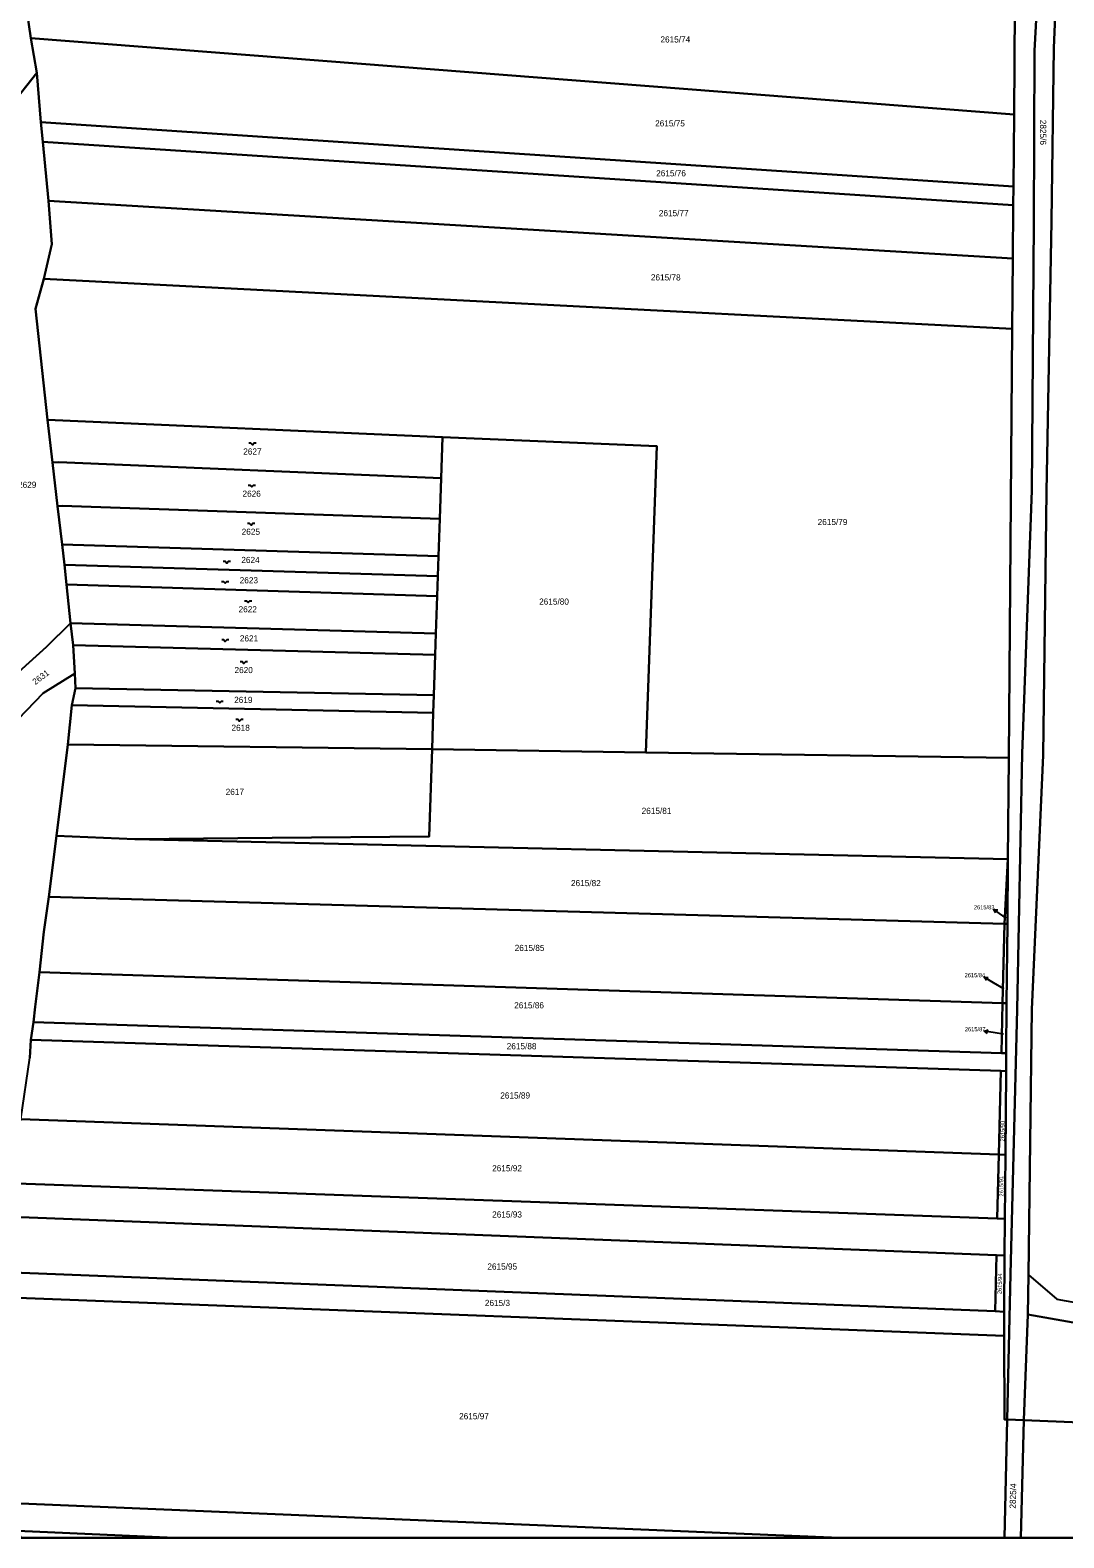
# Model space of a CAD drawing. Extents: x -596024 to -594475, y -1163820 to -1161957.
# Drawn here: x -595164.4 to -594879.1, y -1163820.2 to -1163404 of the extents above; entities that cross this region are included whole.
import ezdxf

# ---------------------------------------------------------------- set-up
doc = ezdxf.new("R2010")
doc.units = 0
for name, color, linetype in [('Level 1', 7, 'Continuous'), ('Level 4', 7, 'Continuous'), ('Level 5', 7, 'Continuous'), ('Level 57', 7, 'Continuous'), ('Level 60', 7, 'Continuous'), ('Vrstva 60', 7, 'Continuous'), ('Vrstva 63', 7, 'Continuous')]:
    doc.layers.add(name, color=color, linetype=linetype)

msp = doc.modelspace()

# ---------------------------------------------------------------- linework, layer by layer
at = {"layer": 'Level 1'}
for p, q in [((-594895.48, -1163820.23), (-594894.71, -1163787.59)), ((-594890.11, -1163787.78), (-594890.98, -1163820.23)), ((-595171.38, -1163810.61), (-594941.03, -1163820.23)), ((-595167.87, -1163818.34), (-595124.58, -1163820.23))]:
    msp.add_line(p, q, dxfattribs=at)
for points in [[(-594894.71, -1163787.59), (-594893.79, -1163747.41), (-594892.03, -1163674.4), (-594890.62, -1163603.73), (-594887.9, -1163531.14), (-594887.39, -1163457.21), (-594887.16, -1163409.69), (-594885.8, -1163384.09), (-594882.1, -1163335.97), (-594881.32, -1163308.47), (-594889.29, -1163183.24), (-594889.61, -1163167.04), (-594890.11, -1163145.09)], [(-594888.88, -1163747.67), (-594887.95, -1163674.37), (-594884.78, -1163604.15), (-594883.87, -1163531.43), (-594882.54, -1163456.78), (-594881.9, -1163408.92), (-594880.83, -1163384.76), (-594876.89, -1163338.79)], [(-595164.21, -1163406.27), (-595168.62, -1163375.94)], [(-594892.61, -1163398), (-594892.85, -1163427.31)], [(-594892.85, -1163427.31), (-595164.21, -1163406.27)], [(-595164.21, -1163406.27), (-595162.62, -1163415.85)], [(-595169.81, -1163424.99), (-595162.62, -1163415.85)], [(-595162.62, -1163415.85), (-595161.46, -1163429.42)], [(-594893.01, -1163447.21), (-594892.85, -1163427.31)], [(-595161.46, -1163429.42), (-595160.94, -1163434.83)], [(-595161.46, -1163429.42), (-594893.01, -1163447.21)], [(-595160.94, -1163434.83), (-595159.39, -1163451.17)], [(-594893.06, -1163452.31), (-595160.94, -1163434.83)], [(-594893.01, -1163447.21), (-594893.06, -1163452.31)], [(-595160.65, -1163472.63), (-595158.4, -1163463.07), (-595159.39, -1163451.17)], [(-595159.39, -1163451.17), (-594893.18, -1163467.09)], [(-594893.06, -1163452.31), (-594893.18, -1163467.09)], [(-594893.18, -1163467.09), (-594893.34, -1163486.47)], [(-595159.6, -1163511.56), (-595162.92, -1163480.95), (-595160.65, -1163472.63)], [(-594893.34, -1163486.47), (-595160.65, -1163472.63)], [(-594893.34, -1163486.47), (-594894.33, -1163604.93)], [(-595159.6, -1163511.56), (-595050.61, -1163516.35)], [(-595158.22, -1163523.39), (-595159.6, -1163511.56)], [(-595050.99, -1163527.66), (-595050.61, -1163516.35)], [(-594994.44, -1163603.44), (-594991.44, -1163518.91), (-595050.61, -1163516.35)], [(-595158.22, -1163523.39), (-595156.51, -1163523.29), (-595050.99, -1163527.66)], [(-595156.83, -1163535.39), (-595158.22, -1163523.39)], [(-595051.37, -1163538.89), (-595050.99, -1163527.66)], [(-595156.83, -1163535.39), (-595155.55, -1163535.32), (-595051.37, -1163538.89)], [(-595155.59, -1163546.03), (-595156.83, -1163535.39)], [(-595051.71, -1163549.26), (-595051.37, -1163538.89)], [(-595051.71, -1163549.26), (-595155.59, -1163546.03)], [(-595154.91, -1163551.65), (-595155.59, -1163546.03)], [(-595154.91, -1163551.65), (-595051.9, -1163554.78)], [(-595154.39, -1163557.04), (-595154.91, -1163551.65)], [(-595051.9, -1163554.78), (-595051.71, -1163549.26)], [(-595052.08, -1163560.23), (-595051.9, -1163554.78)], [(-595052.08, -1163560.23), (-595154.39, -1163557.04)], [(-595153.32, -1163567.77), (-595154.39, -1163557.04)], [(-595052.43, -1163570.6), (-595052.08, -1163560.23)], [(-595173.55, -1163598.4), (-595171.45, -1163584.7), (-595159.88, -1163574.29), (-595153.32, -1163567.77)], [(-595153.32, -1163567.77), (-595052.43, -1163570.6)], [(-595152.55, -1163573.8), (-595153.32, -1163567.77)], [(-595052.62, -1163576.43), (-595052.43, -1163570.6)], [(-595152.12, -1163581.59), (-595152.55, -1163573.8)], [(-595052.62, -1163576.43), (-595152.55, -1163573.8)], [(-595052.99, -1163587.58), (-595052.62, -1163576.43)], [(-595152.12, -1163581.59), (-595160.81, -1163587.04), (-595167.71, -1163594.27), (-595170.35, -1163599.68), (-595174.49, -1163637.45), (-595176.11, -1163658.53), (-595174.49, -1163676.29), (-595174.69, -1163688.93), (-595176.27, -1163699.8), (-595179.65, -1163708.43), (-595181.95, -1163711.02), (-595190.69, -1163714.93), (-595195.82, -1163716.42)], [(-595151.89, -1163585.68), (-595152.12, -1163581.59)], [(-595152.94, -1163590.36), (-595151.89, -1163585.68)], [(-595151.89, -1163585.68), (-595052.99, -1163587.58)], [(-595053.16, -1163592.45), (-595052.99, -1163587.58)], [(-595154.03, -1163601.25), (-595152.94, -1163590.36)], [(-595152.94, -1163590.36), (-595053.16, -1163592.45)], [(-595053.49, -1163602.5), (-595053.16, -1163592.45)], [(-595157.12, -1163626.46), (-595154.03, -1163601.25)], [(-595154.03, -1163601.25), (-595053.49, -1163602.5)], [(-595135.55, -1163627.33), (-595097.61, -1163626.99), (-595054.3, -1163626.6), (-595053.49, -1163602.5)], [(-595053.49, -1163602.5), (-594994.44, -1163603.44)], [(-594894.33, -1163604.93), (-594994.44, -1163603.44)], [(-594894.33, -1163604.93), (-594894.56, -1163632.87)], [(-595157.12, -1163626.46), (-595159.23, -1163643.27)], [(-595157.12, -1163626.46), (-595135.55, -1163627.33)], [(-594894.56, -1163632.87), (-595135.55, -1163627.33)], [(-594895.48, -1163650.69), (-594894.56, -1163632.87)], [(-594894.56, -1163632.87), (-594894.7, -1163650.71)], [(-595161.84, -1163664.1), (-595160.69, -1163652.94), (-595159.23, -1163643.27)], [(-595159.23, -1163643.27), (-594895.48, -1163650.69)], [(-594895.48, -1163650.69), (-594896.02, -1163672.62)], [(-594894.7, -1163650.71), (-594895.48, -1163650.69)], [(-594894.89, -1163672.67), (-594894.7, -1163650.71)], [(-595163.49, -1163677.92), (-595163, -1163673.62), (-595161.84, -1163664.1)], [(-594896.02, -1163672.62), (-595161.84, -1163664.1)], [(-594896.35, -1163686.42), (-594896.02, -1163672.62)], [(-594896.02, -1163672.62), (-594894.89, -1163672.67)], [(-594894.89, -1163672.67), (-594895, -1163686.46)], [(-595164.26, -1163682.78), (-595163.49, -1163677.92)], [(-595163.49, -1163677.92), (-594896.35, -1163686.42)], [(-595166.98, -1163704.63), (-595164.54, -1163687.76), (-595164.26, -1163682.78)], [(-594896.47, -1163691.35), (-595164.26, -1163682.78)], [(-594895, -1163686.46), (-594896.35, -1163686.42)], [(-594895.04, -1163691.39), (-594895, -1163686.46)], [(-594897.04, -1163714.39), (-594896.47, -1163691.35)], [(-594896.47, -1163691.35), (-594895.04, -1163691.39)], [(-594895.04, -1163691.39), (-594895.23, -1163714.46)], [(-595166.98, -1163704.63), (-594897.04, -1163714.39)], [(-594897.48, -1163732.08), (-594897.04, -1163714.39)], [(-594895.23, -1163714.46), (-594897.04, -1163714.39)], [(-594895.37, -1163732.16), (-594895.23, -1163714.46)], [(-595173.34, -1163722.2), (-594897.48, -1163732.08)], [(-595176.58, -1163731.36), (-594897.72, -1163742.15)], [(-594897.48, -1163732.08), (-594895.37, -1163732.16)], [(-594895.37, -1163732.16), (-594895.46, -1163742.25)], [(-594897.72, -1163742.15), (-594898.1, -1163757.7)], [(-594895.46, -1163742.25), (-594897.72, -1163742.15)], [(-594895.59, -1163757.8), (-594895.46, -1163742.25)], [(-594898.1, -1163757.7), (-595178.58, -1163746.62)], [(-594888.88, -1163747.67), (-594889.06, -1163758.56)], [(-594888.88, -1163747.67), (-594881.07, -1163754.37), (-594853.71, -1163759.18), (-594809.52, -1163766.35), (-594779.42, -1163772.07), (-594705.71, -1163784.41), (-594630.48, -1163797), (-594524.52, -1163814.91)], [(-595177.46, -1163753.59), (-594895.57, -1163764.46)], [(-594895.59, -1163757.8), (-594898.1, -1163757.7)], [(-594895.59, -1163757.8), (-594895.57, -1163764.46)], [(-594889.06, -1163758.56), (-594890.11, -1163787.78)], [(-594661.02, -1163797.43), (-594706.83, -1163789.82), (-594781.05, -1163777.75), (-594810.04, -1163772.05), (-594854.05, -1163764.77), (-594889.06, -1163758.56)], [(-594895.57, -1163764.46), (-594895.52, -1163787.56), (-594894.71, -1163787.59)], [(-594894.71, -1163787.59), (-594890.11, -1163787.78)], [(-594890.11, -1163787.78), (-594739.19, -1163793.96)]]:
    msp.add_lwpolyline(points, dxfattribs=at)
at = {"layer": 'Level 5'}
for points in [[(-595104.07, -1163517.99), (-595103.57, -1163517.99), (-595103.07, -1163518.49), (-595102.57, -1163517.99), (-595102.07, -1163517.99)], [(-595104.25, -1163529.63), (-595103.75, -1163529.63), (-595103.25, -1163530.13), (-595102.75, -1163529.63), (-595102.25, -1163529.63)], [(-595104.44, -1163540.14), (-595103.94, -1163540.14), (-595103.44, -1163540.64), (-595102.94, -1163540.14), (-595102.44, -1163540.14)], [(-595111.13, -1163550.63), (-595110.63, -1163550.63), (-595110.13, -1163551.13), (-595109.63, -1163550.63), (-595109.13, -1163550.63)], [(-595111.59, -1163556.23), (-595111.09, -1163556.23), (-595110.59, -1163556.73), (-595110.09, -1163556.23), (-595109.59, -1163556.23)], [(-595105.26, -1163561.54), (-595104.76, -1163561.54), (-595104.26, -1163562.04), (-595103.76, -1163561.54), (-595103.26, -1163561.54)], [(-595111.55, -1163572.27), (-595111.05, -1163572.27), (-595110.55, -1163572.77), (-595110.05, -1163572.27), (-595109.55, -1163572.27)], [(-595106.43, -1163578.32), (-595105.93, -1163578.32), (-595105.43, -1163578.82), (-595104.93, -1163578.32), (-595104.43, -1163578.32)], [(-595113.11, -1163589.26), (-595112.61, -1163589.26), (-595112.11, -1163589.76), (-595111.61, -1163589.26), (-595111.11, -1163589.26)], [(-595107.63, -1163594.25), (-595107.13, -1163594.25), (-595106.63, -1163594.75), (-595106.13, -1163594.25), (-595105.63, -1163594.25)]]:
    msp.add_lwpolyline(points, dxfattribs=at)
at = {"layer": 'Level 57'}
for p, q in [((-594895.98, -1163648.49), (-594898.41, -1163646.73)), ((-594895.04, -1163649.16), (-594895.98, -1163648.49)), ((-594898.49, -1163666.99), (-594901.08, -1163665.47)), ((-594895.64, -1163668.66), (-594898.49, -1163666.99)), ((-594898.08, -1163680.82), (-594901.05, -1163680.38)), ((-594895.72, -1163681.18), (-594898.08, -1163680.82))]:
    msp.add_line(p, q, dxfattribs=at)
for points in [[(-594897.89, -1163647.72), (-594898.41, -1163646.73), (-594897.31, -1163646.91)], [(-594900.47, -1163666.41), (-594901.08, -1163665.47), (-594899.96, -1163665.54)], [(-594900.14, -1163681.02), (-594901.05, -1163680.38), (-594899.99, -1163680.03)]]:
    msp.add_lwpolyline(points, dxfattribs=at)
at = {"layer": 'Level 60'}
for points in [[(-594876.89, -1163338.79), (-594880.83, -1163384.76), (-594881.9, -1163408.92), (-594882.54, -1163456.78), (-594883.87, -1163531.43), (-594884.78, -1163604.15), (-594887.95, -1163674.37), (-594888.88, -1163747.67), (-594889.06, -1163758.56), (-594890.11, -1163787.78), (-594894.71, -1163787.59), (-594893.79, -1163747.41), (-594892.03, -1163674.4), (-594890.62, -1163603.73), (-594887.9, -1163531.14), (-594887.39, -1163457.21), (-594887.16, -1163409.69), (-594885.8, -1163384.09), (-594882.1, -1163335.97), (-594881.32, -1163308.47), (-594889.29, -1163183.24), (-594889.61, -1163167.04), (-594890.11, -1163145.09)], [(-594885.8, -1163384.09), (-594887.16, -1163409.69), (-594887.39, -1163457.21), (-594887.9, -1163531.14), (-594890.62, -1163603.73), (-594892.03, -1163674.4), (-594893.79, -1163747.41), (-594894.71, -1163787.59), (-594895.52, -1163787.56), (-594895.57, -1163764.46), (-594895.59, -1163757.8), (-594895.46, -1163742.25), (-594895.37, -1163732.16), (-594895.23, -1163714.46), (-594895.04, -1163691.39), (-594895, -1163686.46), (-594894.89, -1163672.67), (-594894.7, -1163650.71), (-594894.56, -1163632.87), (-594894.33, -1163604.93), (-594893.34, -1163486.47), (-594893.18, -1163467.09), (-594893.06, -1163452.31), (-594893.01, -1163447.21), (-594892.85, -1163427.31), (-594892.61, -1163398)], [(-595169.81, -1163424.99), (-595162.62, -1163415.85), (-595161.46, -1163429.42), (-595160.94, -1163434.83), (-595159.39, -1163451.17), (-595158.4, -1163463.07), (-595160.65, -1163472.63), (-595162.92, -1163480.95), (-595159.6, -1163511.56), (-595158.22, -1163523.39), (-595156.83, -1163535.39), (-595155.59, -1163546.03), (-595154.91, -1163551.65), (-595154.39, -1163557.04), (-595153.32, -1163567.77), (-595159.88, -1163574.29), (-595171.45, -1163584.7)], [(-595171.45, -1163584.7), (-595159.88, -1163574.29), (-595153.32, -1163567.77), (-595152.55, -1163573.8), (-595152.12, -1163581.59), (-595160.81, -1163587.04), (-595167.71, -1163594.27)], [(-595167.71, -1163594.27), (-595160.81, -1163587.04), (-595152.12, -1163581.59), (-595151.89, -1163585.68), (-595152.94, -1163590.36), (-595154.03, -1163601.25), (-595157.12, -1163626.46), (-595159.23, -1163643.27), (-595160.69, -1163652.94), (-595161.84, -1163664.1), (-595163, -1163673.62), (-595163.49, -1163677.92), (-595164.26, -1163682.78), (-595164.54, -1163687.76)]]:
    msp.add_lwpolyline(points, dxfattribs=at)
for points in [[(-595169.37, -1163381.98), (-595168.62, -1163375.94), (-595164.21, -1163406.27), (-595162.62, -1163415.85), (-595169.81, -1163424.99), (-595173.36, -1163424.93), (-595171.94, -1163414.75), (-595170.3, -1163393.85)], [(-595168.62, -1163375.94), (-594892.61, -1163398), (-594892.85, -1163427.31), (-595164.21, -1163406.27)], [(-595164.21, -1163406.27), (-594892.85, -1163427.31), (-594893.01, -1163447.21), (-595161.46, -1163429.42), (-595162.62, -1163415.85)], [(-595160.94, -1163434.83), (-595161.46, -1163429.42), (-594893.01, -1163447.21), (-594893.06, -1163452.31)], [(-595159.39, -1163451.17), (-595160.94, -1163434.83), (-594893.06, -1163452.31), (-594893.18, -1163467.09)], [(-594893.18, -1163467.09), (-594893.34, -1163486.47), (-595160.65, -1163472.63), (-595158.4, -1163463.07), (-595159.39, -1163451.17)], [(-594893.34, -1163486.47), (-594894.33, -1163604.93), (-594994.44, -1163603.44), (-594991.44, -1163518.91), (-595050.61, -1163516.35), (-595159.6, -1163511.56), (-595162.92, -1163480.95), (-595160.65, -1163472.63)], [(-595158.22, -1163523.39), (-595159.6, -1163511.56), (-595050.61, -1163516.35), (-595050.99, -1163527.66), (-595156.51, -1163523.29)], [(-594991.44, -1163518.91), (-594994.44, -1163603.44), (-595053.49, -1163602.5), (-595053.16, -1163592.45), (-595052.99, -1163587.58), (-595052.62, -1163576.43), (-595052.43, -1163570.6), (-595052.08, -1163560.23), (-595051.9, -1163554.78), (-595051.71, -1163549.26), (-595051.37, -1163538.89), (-595050.99, -1163527.66), (-595050.61, -1163516.35)], [(-595155.55, -1163535.32), (-595156.83, -1163535.39), (-595158.22, -1163523.39), (-595156.51, -1163523.29), (-595050.99, -1163527.66), (-595051.37, -1163538.89)], [(-595155.59, -1163546.03), (-595156.83, -1163535.39), (-595155.55, -1163535.32), (-595051.37, -1163538.89), (-595051.71, -1163549.26)], [(-595154.91, -1163551.65), (-595155.59, -1163546.03), (-595051.71, -1163549.26), (-595051.9, -1163554.78)], [(-595154.39, -1163557.04), (-595154.91, -1163551.65), (-595051.9, -1163554.78), (-595052.08, -1163560.23)], [(-595153.32, -1163567.77), (-595154.39, -1163557.04), (-595052.08, -1163560.23), (-595052.43, -1163570.6)], [(-595152.55, -1163573.8), (-595153.32, -1163567.77), (-595052.43, -1163570.6), (-595052.62, -1163576.43)], [(-595151.89, -1163585.68), (-595152.12, -1163581.59), (-595152.55, -1163573.8), (-595052.62, -1163576.43), (-595052.99, -1163587.58)], [(-595152.94, -1163590.36), (-595151.89, -1163585.68), (-595052.99, -1163587.58), (-595053.16, -1163592.45)], [(-595154.03, -1163601.25), (-595152.94, -1163590.36), (-595053.16, -1163592.45), (-595053.49, -1163602.5)], [(-595097.61, -1163626.99), (-595135.55, -1163627.33), (-595157.12, -1163626.46), (-595154.03, -1163601.25), (-595053.49, -1163602.5), (-595054.3, -1163626.6)], [(-594994.44, -1163603.44), (-594894.33, -1163604.93), (-594894.56, -1163632.87), (-595135.55, -1163627.33), (-595097.61, -1163626.99), (-595054.3, -1163626.6), (-595053.49, -1163602.5)], [(-594894.56, -1163632.87), (-594895.48, -1163650.69), (-595159.23, -1163643.27), (-595157.12, -1163626.46), (-595135.55, -1163627.33)], [(-594895.48, -1163650.69), (-594894.56, -1163632.87), (-594894.7, -1163650.71)], [(-594895.48, -1163650.69), (-594896.02, -1163672.62), (-595161.84, -1163664.1), (-595160.69, -1163652.94), (-595159.23, -1163643.27)], [(-594895.48, -1163650.69), (-594894.7, -1163650.71), (-594894.89, -1163672.67), (-594896.02, -1163672.62)], [(-594896.02, -1163672.62), (-594896.35, -1163686.42), (-595163.49, -1163677.92), (-595163, -1163673.62), (-595161.84, -1163664.1)], [(-594896.02, -1163672.62), (-594894.89, -1163672.67), (-594895, -1163686.46), (-594896.35, -1163686.42)], [(-594896.35, -1163686.42), (-594895, -1163686.46), (-594895.04, -1163691.39), (-594896.47, -1163691.35), (-595164.26, -1163682.78), (-595163.49, -1163677.92)], [(-594896.47, -1163691.35), (-594897.04, -1163714.39), (-595166.98, -1163704.63), (-595164.54, -1163687.76), (-595164.26, -1163682.78)], [(-594896.47, -1163691.35), (-594895.04, -1163691.39), (-594895.23, -1163714.46), (-594897.04, -1163714.39)], [(-594897.48, -1163732.08), (-595173.34, -1163722.2), (-595166.98, -1163704.63), (-594897.04, -1163714.39)], [(-594897.04, -1163714.39), (-594895.23, -1163714.46), (-594895.37, -1163732.16), (-594897.48, -1163732.08)], [(-595173.34, -1163722.2), (-594897.48, -1163732.08), (-594895.37, -1163732.16), (-594895.46, -1163742.25), (-594897.72, -1163742.15), (-595176.58, -1163731.36)], [(-594897.72, -1163742.15), (-594898.1, -1163757.7), (-595178.58, -1163746.62), (-595179.19, -1163742.77), (-595179.34, -1163739.16), (-595176.58, -1163731.36)], [(-594897.72, -1163742.15), (-594895.46, -1163742.25), (-594895.59, -1163757.8), (-594898.1, -1163757.7)], [(-595182.99, -1163753.38), (-595181.93, -1163746.49), (-595178.58, -1163746.62), (-594898.1, -1163757.7), (-594895.59, -1163757.8), (-594895.57, -1163764.46), (-595177.46, -1163753.59)], [(-594889.06, -1163758.56), (-594888.88, -1163747.67), (-594881.07, -1163754.37), (-594853.71, -1163759.18), (-594809.52, -1163766.35), (-594779.42, -1163772.07), (-594705.71, -1163784.41), (-594630.48, -1163797), (-594524.52, -1163814.91), (-594562.06, -1163810.84), (-594616.78, -1163804.65), (-594631.17, -1163802.24), (-594661.02, -1163797.43), (-594706.83, -1163789.82), (-594781.05, -1163777.75), (-594810.04, -1163772.05), (-594854.05, -1163764.77)], [(-594739.19, -1163793.96), (-594890.11, -1163787.78), (-594889.06, -1163758.56), (-594854.05, -1163764.77), (-594810.04, -1163772.05), (-594781.05, -1163777.75), (-594706.83, -1163789.82), (-594661.02, -1163797.43)]]:
    msp.add_lwpolyline(points, close=True, dxfattribs=at)
at = {"layer": 'Vrstva 60'}
msp.add_lwpolyline([(-594876.89, -1163338.79), (-594880.83, -1163384.76), (-594881.9, -1163408.92), (-594882.54, -1163456.78), (-594883.87, -1163531.43), (-594884.78, -1163604.15), (-594887.95, -1163674.37), (-594888.88, -1163747.67), (-594881.07, -1163754.37), (-594853.71, -1163759.18)], dxfattribs=at)
for points in [[(-594941.03, -1163820.23), (-594895.48, -1163820.23), (-594894.71, -1163787.59), (-594895.52, -1163787.56), (-594895.57, -1163764.46), (-595177.46, -1163753.59), (-595176.41, -1163760.21), (-595181.57, -1163788.15), (-595171.38, -1163810.61)], [(-594895.48, -1163820.23), (-594890.98, -1163820.23), (-594890.11, -1163787.78), (-594894.71, -1163787.59)], [(-594890.98, -1163820.23), (-594742.78, -1163820.23), (-594739.19, -1163793.96), (-594890.11, -1163787.78)], [(-595124.58, -1163820.23), (-594941.03, -1163820.23), (-595171.38, -1163810.61), (-595167.87, -1163818.34)], [(-595167.01, -1163820.23), (-595124.58, -1163820.23), (-595167.87, -1163818.34)]]:
    msp.add_lwpolyline(points, close=True, dxfattribs=at)
at = {"layer": 'Vrstva 63'}
msp.add_lwpolyline([(-594475.47, -1163820.23), (-596024.42, -1163820.23), (-596024.42, -1161956.88), (-594475.47, -1161956.88)], close=True, dxfattribs=at)

# ---------------------------------------------------------------- texts
at = {"layer": 'Level 4'}
for s, height, p in [('2615/74', 1.7, (-594990.45, -1163407.43)), ('2615/75', 1.7, (-594991.92, -1163430.6)), ('2615/76', 1.7, (-594991.63, -1163444.38)), ('2615/77', 1.7, (-594990.89, -1163455.38)), ('2615/78', 1.7, (-594993.09, -1163473.12)), ('2627', 1.7, (-595105.6, -1163521.19)), ('2629', 1.7, (-595167.77, -1163530.38)), ('2626', 1.7, (-595105.81, -1163532.83)), ('2615/79', 1.7, (-594947.06, -1163540.65)), ('2625', 1.7, (-595106.04, -1163543.34)), ('2624', 1.7, (-595106.13, -1163551.13)), ('2623', 1.7, (-595106.59, -1163556.73)), ('2615/80', 1.7, (-595023.93, -1163562.62)), ('2622', 1.7, (-595106.89, -1163564.74)), ('2621', 1.7, (-595106.55, -1163572.77)), ('2620', 1.7, (-595108.02, -1163581.52)), ('2619', 1.7, (-595108.11, -1163589.76)), ('2618', 1.7, (-595108.85, -1163597.45)), ('2617', 1.7, (-595110.45, -1163615.14)), ('2615/81', 1.7, (-594995.64, -1163620.39)), ('2615/82', 1.7, (-595015.14, -1163640.33)), ('2615/83', 0.1, (-594895.04, -1163649.16)), ('2615/85', 1.7, (-595030.68, -1163658.23)), ('2615/84', 0.1, (-594895.64, -1163668.66)), ('2615/86', 1.7, (-595030.82, -1163674.07)), ('2615/87', 0.1, (-594895.72, -1163681.18)), ('2615/88', 1.7, (-595032.88, -1163685.36)), ('2615/89', 1.7, (-595034.66, -1163698.96)), ('2615/92', 1.7, (-595036.9, -1163719.05)), ('2615/93', 1.7, (-595036.9, -1163731.81)), ('2615/95', 1.7, (-595038.22, -1163746.18)), ('2615/3', 1.7, (-595038.92, -1163756.23)), ('2615/97', 1.7, (-595046.02, -1163787.5))]:
    msp.add_text(s, height=height, dxfattribs=at).set_placement(p)
for s, height, rotation, p in [('2825/6', 1.7, 269.7227, (-594885.65, -1163428.77)), ('2631', 1.7, 37.035, (-595163, -1163584.85)), ('2615/90', 1.14, 88.9191, (-594895.52, -1163710.81)), ('2615/91', 1.14, 90.6879, (-594895.77, -1163726.01)), ('2615/94', 1.14, 88.1118, (-594896.32, -1163752.97)), ('2825/4', 1.7, 88.0799, (-594892.41, -1163812.18))]:
    msp.add_text(s, height=height, rotation=rotation, dxfattribs=at).set_placement(p)
at = {"layer": 'Level 57'}
for s, p in [('2615/83', (-594903.94, -1163646.73)), ('2615/84', (-594906.51, -1163665.47)), ('2615/87', (-594906.43, -1163680.38))]:
    msp.add_text(s, height=1.14, dxfattribs=at).set_placement(p)

doc.saveas('drawing.dxf')
